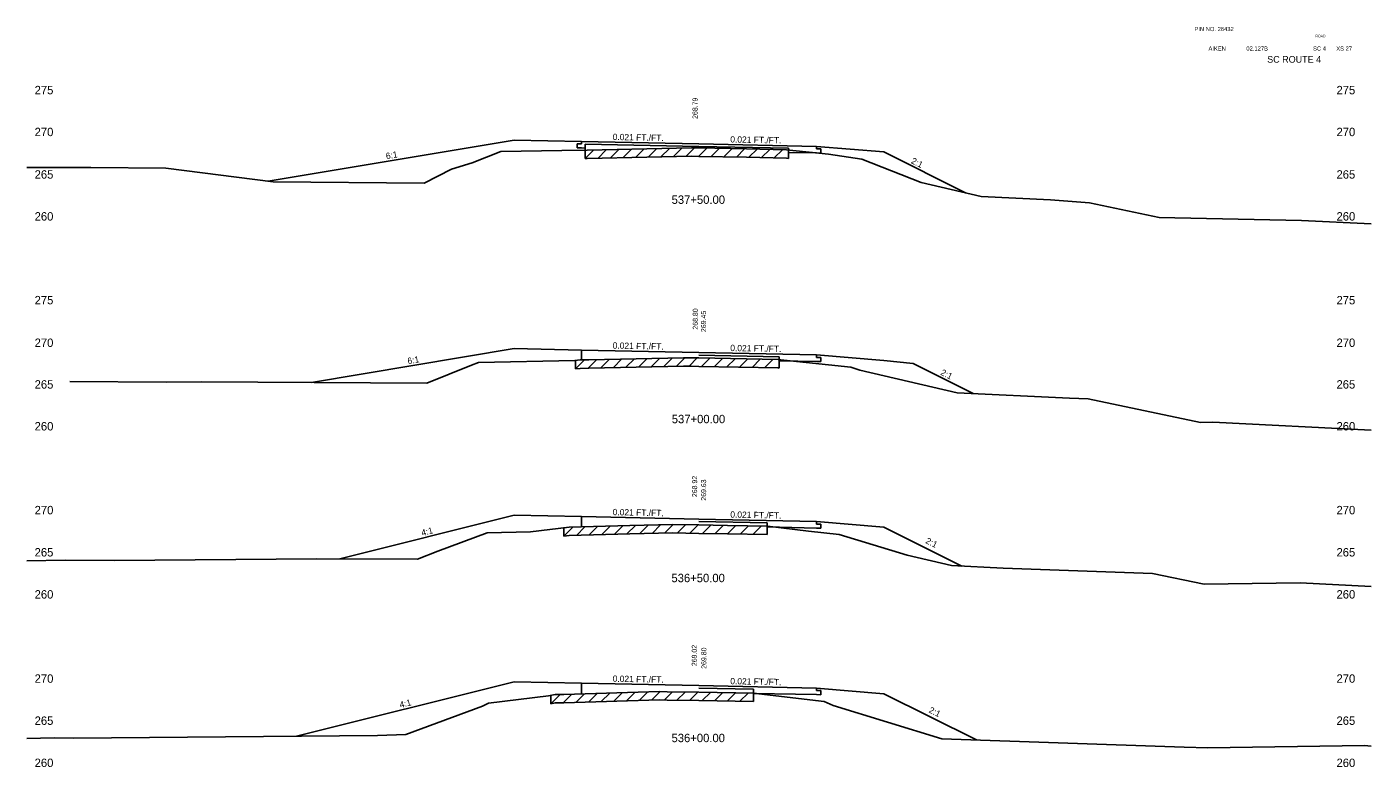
# Model space of a CAD drawing. Extents: x 883 to 1160, y 1002 to 4323.
# Drawn here: x 1000 to 1160, y 4005.1 to 4093.2 of the extents above; entities that cross this region are included whole.
import ezdxf

# ---------------------------------------------------------------- set-up
doc = ezdxf.new("R2010")
doc.units = 0
for name, color, linetype in [('Level 1', 7, 'Continuous'), ('Level 10', 7, 'Continuous'), ('Level 11', 7, 'Continuous'), ('Level 12', 7, 'Continuous'), ('Level 3', 7, 'Continuous'), ('Level 32', 7, 'Continuous'), ('Level 53', 7, 'Continuous'), ('Level 59', 7, 'Continuous'), ('Level 6', 7, 'Continuous'), ('Level 60', 7, 'Continuous'), ('Level 61', 7, 'Continuous'), ('Level 7', 7, 'Continuous')]:
    doc.layers.add(name, color=color, linetype=linetype)

msp = doc.modelspace()

# ---------------------------------------------------------------- linework, layer by layer
at = {"layer": 'Level 11'}
for p, q in [((1066, 4079.27), (1065.5, 4079.28)), ((1065.5, 4079.28), (1065.5, 4078.8)), ((1065.5, 4078.8), (1066, 4078.79)), ((1066, 4079.57), (1066, 4079.27)), ((1094, 4078.68), (1094, 4078.98)), ((1094.5, 4078.67), (1094, 4078.68)), ((1094.5, 4078.19), (1094.5, 4078.67)), ((1094, 4078.2), (1094.5, 4078.19)), ((1066, 4053.57), (1066, 4054.74)), ((1094, 4053.86), (1094, 4054.16)), ((1094.5, 4053.85), (1094, 4053.86)), ((1094, 4053.38), (1094.5, 4053.37)), ((1094.5, 4053.37), (1094.5, 4053.85)), ((1066, 4033.69), (1066, 4034.92)), ((1094, 4034.03), (1094, 4034.33)), ((1094.5, 4034.02), (1094, 4034.03)), ((1094.5, 4033.54), (1094.5, 4034.02)), ((1094, 4033.55), (1094.5, 4033.54)), ((1066, 4013.82), (1066, 4015.09)), ((1094, 4014.21), (1094, 4014.51)), ((1094.5, 4014.2), (1094, 4014.21)), ((1094, 4013.73), (1094.5, 4013.72)), ((1094.5, 4013.72), (1094.5, 4014.2))]:
    msp.add_line(p, q, dxfattribs=at)
at = {"layer": 'Level 12'}
for p, q in [((1066.44, 4078.78), (1066, 4078.79)), ((1066.44, 4078.52), (1066.44, 4078.78)), ((1090.64, 4078.54), (1090.64, 4078.27)), ((1090.64, 4078.27), (1094, 4078.2)), ((1089.55, 4053.6), (1089.55, 4053.47)), ((1089.55, 4053.47), (1094, 4053.38)), ((1088.11, 4033.77), (1088.11, 4033.68)), ((1088.11, 4033.68), (1094, 4033.55)), ((1086.5, 4013.91), (1086.5, 4013.88)), ((1086.5, 4013.88), (1094, 4013.73))]:
    msp.add_line(p, q, dxfattribs=at)
at = {"layer": 'Level 53'}
for p, q in [((1080, 4078.98), (1066.44, 4079.26)), ((1066.44, 4079.26), (1066.44, 4078.52)), ((1080, 4078.98), (1090.64, 4078.75)), ((1090.64, 4078.75), (1090.64, 4078.54)), ((1080, 4054.15), (1089.55, 4053.95)), ((1089.55, 4053.95), (1089.55, 4053.6)), ((1080, 4034.33), (1088.11, 4034.16)), ((1088.11, 4034.16), (1088.11, 4033.77)), ((1080, 4014.5), (1086.5, 4014.36)), ((1086.5, 4014.36), (1086.5, 4013.91))]:
    msp.add_line(p, q, dxfattribs=at)
at = {"layer": 'Level 59'}
for p, q in [((1066, 4079.57), (1080, 4079.28)), ((1080, 4079.28), (1094, 4078.98)), ((1066, 4054.74), (1080, 4054.45)), ((1080, 4054.45), (1094, 4054.16)), ((1066, 4034.92), (1080, 4034.63)), ((1080, 4034.63), (1094, 4034.33)), ((1066, 4015.09), (1080, 4014.8)), ((1080, 4014.8), (1094, 4014.51))]:
    msp.add_line(p, q, dxfattribs=at)
at = {"layer": 'Level 6'}
for p, q in [((1058, 4079.73), (1066, 4079.57)), ((1094, 4078.98), (1102, 4078.32)), ((1058, 4054.91), (1066, 4054.74)), ((1094, 4054.16), (1102, 4053.49)), ((1102, 4053.49), (1105.5, 4053.14)), ((1058, 4035.08), (1066, 4034.92)), ((1094, 4034.33), (1102, 4033.67)), ((1058, 4015.26), (1066, 4015.09)), ((1094, 4014.51), (1102, 4013.84))]:
    msp.add_line(p, q, dxfattribs=at)
at = {"layer": 'Level 60'}
for p, q in [((1056.41, 4078.36), (1063.66, 4078.51)), ((1063.66, 4078.51), (1066.69, 4078.52)), ((1066.69, 4078.52), (1073.81, 4078.68)), ((1073.81, 4078.68), (1079.09, 4078.81)), ((1079.09, 4078.81), (1080, 4078.79)), ((1080, 4078.79), (1085.64, 4078.68)), ((1085.64, 4078.68), (1090.4, 4078.57)), ((1090.4, 4078.57), (1095.42, 4078.04)), ((1050.55, 4076.26), (1053.01, 4077.01)), ((1053.01, 4077.01), (1056.41, 4078.36)), ((1095.42, 4078.04), (1099.4, 4077.46)), ((1099.4, 4077.46), (1106.44, 4074.69)), ((1000, 4076.46), (1007.62, 4076.46)), ((1007.62, 4076.46), (1016.54, 4076.4)), ((1016.54, 4076.4), (1029.3, 4074.78)), ((1047.27, 4074.62), (1050.55, 4076.26)), ((1029.3, 4074.78), (1047.27, 4074.62)), ((1106.44, 4074.69), (1113.6, 4073.02)), ((1113.6, 4073.02), (1121.82, 4072.62)), ((1121.82, 4072.62), (1126.47, 4072.25)), ((1126.47, 4072.25), (1134.79, 4070.51)), ((1134.79, 4070.51), (1151.71, 4070.16)), ((1151.71, 4070.16), (1160, 4069.75)), ((1047.6, 4050.81), (1052.94, 4052.94)), ((1052.94, 4052.94), (1053.77, 4053.25)), ((1053.77, 4053.25), (1065.22, 4053.48)), ((1065.22, 4053.48), (1065.86, 4053.56)), ((1065.86, 4053.56), (1066.89, 4053.59)), ((1066.89, 4053.59), (1078.14, 4053.83)), ((1078.14, 4053.83), (1079.05, 4053.82)), ((1079.05, 4053.82), (1080, 4053.8)), ((1080, 4053.8), (1089.42, 4053.61)), ((1089.42, 4053.61), (1090.09, 4053.53)), ((1090.09, 4053.53), (1098.06, 4052.69)), ((1098.06, 4052.69), (1099.16, 4052.35)), ((1099.16, 4052.35), (1110.71, 4049.66)), ((1005.12, 4050.98), (1016.56, 4050.92)), ((1016.56, 4050.92), (1020.8, 4050.96)), ((1020.8, 4050.96), (1047.6, 4050.81)), ((1110.71, 4049.66), (1124.09, 4049.03)), ((1124.09, 4049.03), (1126.31, 4048.95)), ((1126.31, 4048.95), (1139.68, 4046.13)), ((1139.68, 4046.13), (1141.17, 4046.15)), ((1141.17, 4046.15), (1160, 4045.22)), ((1059.95, 4033.09), (1064.53, 4033.65)), ((1064.53, 4033.65), (1071.77, 4033.86)), ((1071.77, 4033.86), (1076.89, 4033.97)), ((1076.89, 4033.97), (1080, 4033.92)), ((1080, 4033.92), (1083.41, 4033.86)), ((1083.41, 4033.86), (1088.15, 4033.77)), ((1088.15, 4033.77), (1093.03, 4033.18)), ((1048.9, 4030.81), (1054.78, 4032.98)), ((1054.78, 4032.98), (1059.95, 4033.09)), ((1093.03, 4033.18), (1096.68, 4032.79)), ((1096.68, 4032.79), (1104.76, 4030.31)), ((1046.5, 4029.85), (1048.9, 4030.81)), ((1000, 4029.64), (1004.57, 4029.74)), ((1004.57, 4029.74), (1010.44, 4029.71)), ((1010.44, 4029.71), (1034.48, 4029.91)), ((1034.48, 4029.91), (1046.5, 4029.85)), ((1104.76, 4030.31), (1110.06, 4029.08)), ((1110.06, 4029.08), (1116.21, 4028.78)), ((1116.21, 4028.78), (1133.96, 4028.16)), ((1133.96, 4028.16), (1140.13, 4026.86)), ((1140.13, 4026.86), (1151.56, 4027.03)), ((1151.56, 4027.03), (1160, 4026.61)), ((1054.94, 4012.7), (1062.1, 4013.58)), ((1062.1, 4013.58), (1062.87, 4013.74)), ((1062.87, 4013.74), (1063.93, 4013.76)), ((1063.93, 4013.76), (1075.31, 4014.09)), ((1075.31, 4014.09), (1076.22, 4014.08)), ((1076.22, 4014.08), (1080, 4014.02)), ((1080, 4014.02), (1086.55, 4013.91)), ((1086.55, 4013.91), (1087.12, 4013.83)), ((1087.12, 4013.83), (1094.89, 4012.89)), ((1094.89, 4012.89), (1095.97, 4012.44)), ((1045.11, 4008.98), (1054.23, 4012.36)), ((1054.23, 4012.36), (1054.94, 4012.7)), ((1095.97, 4012.44), (1108.9, 4008.47)), ((1000, 4008.51), (1003.23, 4008.58)), ((1003.23, 4008.58), (1005.54, 4008.56)), ((1005.54, 4008.56), (1041.72, 4008.86)), ((1041.72, 4008.86), (1045.11, 4008.98)), ((1108.9, 4008.47), (1137.73, 4007.46)), ((1137.73, 4007.46), (1140.55, 4007.38)), ((1140.55, 4007.38), (1159.2, 4007.67)), ((1159.2, 4007.67), (1160, 4007.59))]:
    msp.add_line(p, q, dxfattribs=at)
at = {"layer": 'Level 61'}
for p, q in [((1067.46, 4078.54), (1066.44, 4077.52)), ((1066.44, 4078.52), (1066.44, 4077.52)), ((1068.97, 4078.57), (1067.94, 4077.55)), ((1070.47, 4078.61), (1069.44, 4077.58)), ((1071.97, 4078.64), (1070.94, 4077.62)), ((1073.47, 4078.67), (1072.44, 4077.65)), ((1074.97, 4078.71), (1073.94, 4077.68)), ((1076.47, 4078.74), (1075.44, 4077.72)), ((1077.97, 4078.78), (1076.95, 4077.76)), ((1079.45, 4078.8), (1078.45, 4077.79)), ((1080.93, 4078.77), (1079.95, 4077.79)), ((1082.43, 4078.75), (1081.45, 4077.76)), ((1083.93, 4078.72), (1082.95, 4077.74)), ((1085.43, 4078.69), (1084.45, 4077.71)), ((1086.92, 4078.65), (1085.95, 4077.68)), ((1088.42, 4078.62), (1087.45, 4077.64)), ((1089.92, 4078.58), (1088.95, 4077.6)), ((1090.64, 4077.54), (1090.64, 4078.54)), ((1066.44, 4077.52), (1066.69, 4077.52)), ((1066.69, 4077.52), (1073.81, 4077.68)), ((1073.81, 4077.68), (1079.09, 4077.81)), ((1079.09, 4077.81), (1080, 4077.79)), ((1080, 4077.79), (1085.64, 4077.68)), ((1085.64, 4077.68), (1090.4, 4077.57)), ((1090.4, 4077.57), (1090.64, 4077.54)), ((1066.39, 4053.58), (1065.31, 4052.5)), ((1065.31, 4053.5), (1065.31, 4052.5)), ((1067.83, 4053.61), (1066.81, 4052.59)), ((1066.89, 4052.59), (1078.14, 4052.83)), ((1069.33, 4053.65), (1068.31, 4052.62)), ((1070.83, 4053.68), (1069.81, 4052.66)), ((1072.33, 4053.71), (1071.31, 4052.69)), ((1073.83, 4053.74), (1072.81, 4052.72)), ((1075.33, 4053.77), (1074.31, 4052.75)), ((1076.83, 4053.8), (1075.81, 4052.78)), ((1078.33, 4053.83), (1077.31, 4052.81)), ((1078.14, 4052.83), (1079.05, 4052.82)), ((1079.79, 4053.8), (1078.81, 4052.82)), ((1079.05, 4052.82), (1080, 4052.8)), ((1081.29, 4053.77), (1080.31, 4052.79)), ((1082.79, 4053.74), (1081.81, 4052.76)), ((1084.3, 4053.71), (1083.31, 4052.73)), ((1085.8, 4053.69), (1084.81, 4052.7)), ((1087.3, 4053.66), (1086.32, 4052.68)), ((1088.8, 4053.63), (1087.82, 4052.65)), ((1089.55, 4052.6), (1089.55, 4053.6)), ((1065.31, 4052.5), (1065.86, 4052.56)), ((1065.86, 4052.56), (1066.89, 4052.59)), ((1080, 4052.8), (1089.42, 4052.61)), ((1089.42, 4052.61), (1089.55, 4052.6)), ((1064.99, 4033.66), (1063.9, 4032.57)), ((1066.43, 4033.7), (1065.4, 4032.67)), ((1067.93, 4033.75), (1066.9, 4032.72)), ((1069.43, 4033.79), (1068.4, 4032.76)), ((1070.93, 4033.83), (1069.9, 4032.8)), ((1072.43, 4033.87), (1071.41, 4032.85)), ((1073.93, 4033.9), (1072.91, 4032.88)), ((1075.43, 4033.94), (1074.41, 4032.91)), ((1076.93, 4033.97), (1075.91, 4032.95)), ((1078.39, 4033.94), (1077.41, 4032.96)), ((1079.89, 4033.92), (1078.91, 4032.93)), ((1081.39, 4033.89), (1080.41, 4032.91)), ((1082.89, 4033.87), (1081.91, 4032.89)), ((1084.39, 4033.84), (1083.41, 4032.86)), ((1085.89, 4033.81), (1084.91, 4032.83)), ((1087.39, 4033.78), (1086.41, 4032.8)), ((1088.11, 4032.77), (1088.11, 4033.77)), ((1063.9, 4033.57), (1063.9, 4032.57)), ((1063.9, 4032.57), (1064.53, 4032.65)), ((1064.53, 4032.65), (1071.77, 4032.86)), ((1071.77, 4032.86), (1076.89, 4032.97)), ((1076.89, 4032.97), (1080, 4032.92)), ((1080, 4032.92), (1083.41, 4032.86)), ((1083.41, 4032.86), (1088.11, 4032.77)), ((1063.47, 4013.75), (1062.35, 4012.63)), ((1062.35, 4013.63), (1062.35, 4012.63)), ((1064.88, 4013.79), (1063.85, 4012.76)), ((1063.93, 4012.76), (1075.31, 4013.09)), ((1066.38, 4013.84), (1065.35, 4012.81)), ((1067.89, 4013.88), (1066.85, 4012.85)), ((1069.39, 4013.92), (1068.36, 4012.89)), ((1070.89, 4013.97), (1069.86, 4012.94)), ((1072.39, 4014.01), (1071.36, 4012.98)), ((1073.89, 4014.05), (1072.86, 4013.02)), ((1075.39, 4014.09), (1074.36, 4013.07)), ((1075.31, 4013.09), (1076.22, 4013.08)), ((1076.84, 4014.07), (1075.86, 4013.08)), ((1076.22, 4013.08), (1080, 4013.02)), ((1078.35, 4014.04), (1077.36, 4013.06)), ((1079.85, 4014.02), (1078.86, 4013.04)), ((1080, 4013.02), (1086.5, 4012.91)), ((1081.35, 4014), (1080.36, 4013.01)), ((1082.85, 4013.97), (1081.86, 4012.99)), ((1084.35, 4013.95), (1083.36, 4012.96)), ((1085.85, 4013.92), (1084.87, 4012.94)), ((1086.5, 4012.91), (1086.5, 4013.91)), ((1062.35, 4012.63), (1062.87, 4012.74)), ((1062.87, 4012.74), (1063.93, 4012.76))]:
    msp.add_line(p, q, dxfattribs=at)
at = {"layer": 'Level 7'}
for p, q in [((1028.71, 4074.85), (1058, 4079.73)), ((1102, 4078.32), (1111.71, 4073.46)), ((1033.87, 4050.89), (1058, 4054.91)), ((1105.5, 4053.14), (1112.65, 4049.57)), ((1037.25, 4029.9), (1058, 4035.08)), ((1102, 4033.67), (1111.3, 4029.02)), ((1032.08, 4008.78), (1058, 4015.26)), ((1102, 4013.84), (1113.03, 4008.33))]:
    msp.add_line(p, q, dxfattribs=at)

# ---------------------------------------------------------------- texts
at = {"layer": 'Level 1'}
for s, height, p in [('PIN NO. 26432', 0.5, (1138.97, 4092.7)), ('AIKEN', 0.5, (1140.64, 4090.38)), ('02.127B', 0.5, (1145.15, 4090.38)), ('SC ROUTE 4', 0.8, (1147.63, 4088.94)), ('SC 4', 0.5, (1153.09, 4090.38)), ('XS 27', 0.5, (1155.85, 4090.37)), ('537+50.00', 1, (1076.74, 4072.14)), ('537+00.00', 1, (1076.76, 4046.03)), ('536+50.00', 1, (1076.72, 4027.11)), ('536+00.00', 1, (1076.73, 4008.07))]:
    msp.add_text(s, height=height, dxfattribs=at).set_placement(p)
at = {"layer": 'Level 10'}
for s, p in [('268.79', (1079.83, 4082.25)), ('268.80', (1079.86, 4057.17)), ('268.92', (1079.78, 4037.24)), ('269.02', (1079.74, 4017.12))]:
    msp.add_text(s, height=0.6, rotation=90, dxfattribs=at).set_placement(p)
at = {"layer": 'Level 3'}
for s, height, p in [('ROAD', 0.3, (1153.38, 4091.97)), (' 275', 1, (1000.55, 4085.18)), (' 275', 1, (1155.51, 4085.18)), (' 270', 1, (1000.55, 4080.2)), (' 270', 1, (1155.51, 4080.2)), (' 265', 1, (1000.55, 4075.14)), (' 265', 1, (1155.51, 4075.14)), (' 260', 1, (1000.55, 4070.15)), (' 260', 1, (1155.51, 4070.15)), (' 275', 1, (1000.55, 4060.18)), (' 275', 1, (1155.51, 4060.18)), (' 270', 1, (1000.55, 4055.11)), (' 270', 1, (1155.51, 4055.11)), (' 265', 1, (1000.55, 4050.15)), (' 265', 1, (1155.51, 4050.15)), (' 260', 1, (1000.55, 4045.17)), (' 260', 1, (1155.51, 4045.17)), (' 270', 1, (1000.55, 4035.19)), (' 270', 1, (1155.51, 4035.19)), (' 265', 1, (1000.55, 4030.17)), (' 265', 1, (1155.51, 4030.17)), (' 260', 1, (1000.55, 4025.16)), (' 260', 1, (1155.51, 4025.16)), (' 270', 1, (1000.55, 4015.14)), (' 270', 1, (1155.51, 4015.14)), (' 265', 1, (1000.55, 4010.13)), (' 265', 1, (1155.51, 4010.13)), (' 260', 1, (1000.55, 4005.11)), (' 260', 1, (1155.51, 4005.11))]:
    msp.add_text(s, height=height, dxfattribs=at).set_placement(p)
at = {"layer": 'Level 32'}
for s, rotation, p in [('0.021 FT./FT.', 358.8084, (1069.72, 4079.74)), ('0.021 FT./FT.', 358.8084, (1083.72, 4079.45)), ('6:1', 9.4623, (1042.79, 4077.45)), ('2:1', 333.435, (1105.18, 4077.01)), ('0.021 FT./FT.', 358.8084, (1069.72, 4054.91)), ('0.021 FT./FT.', 358.8084, (1083.72, 4054.62)), ('6:1', 9.4623, (1045.37, 4053.06)), ('2:1', 333.435, (1108.68, 4051.83)), ('0.021 FT./FT.', 358.8084, (1069.72, 4035.09)), ('0.021 FT./FT.', 358.8084, (1083.72, 4034.8)), ('4:1', 14.0362, (1047.05, 4032.6)), ('2:1', 333.435, (1106.9, 4031.79)), ('0.021 FT./FT.', 358.8084, (1069.72, 4015.26)), ('0.021 FT./FT.', 358.8084, (1083.72, 4014.97)), ('4:1', 14.0362, (1044.46, 4012.13)), ('2:1', 333.435, (1107.28, 4011.64))]:
    msp.add_text(s, height=0.75, rotation=rotation, dxfattribs=at).set_placement(p)
at = {"layer": 'Level 59'}
for s, p in [(' 269.45', (1080.84, 4056.65)), (' 269.63', (1080.85, 4036.58)), (' 269.80', (1080.88, 4016.57))]:
    msp.add_text(s, height=0.6, rotation=90, dxfattribs=at).set_placement(p)

doc.saveas('drawing.dxf')
